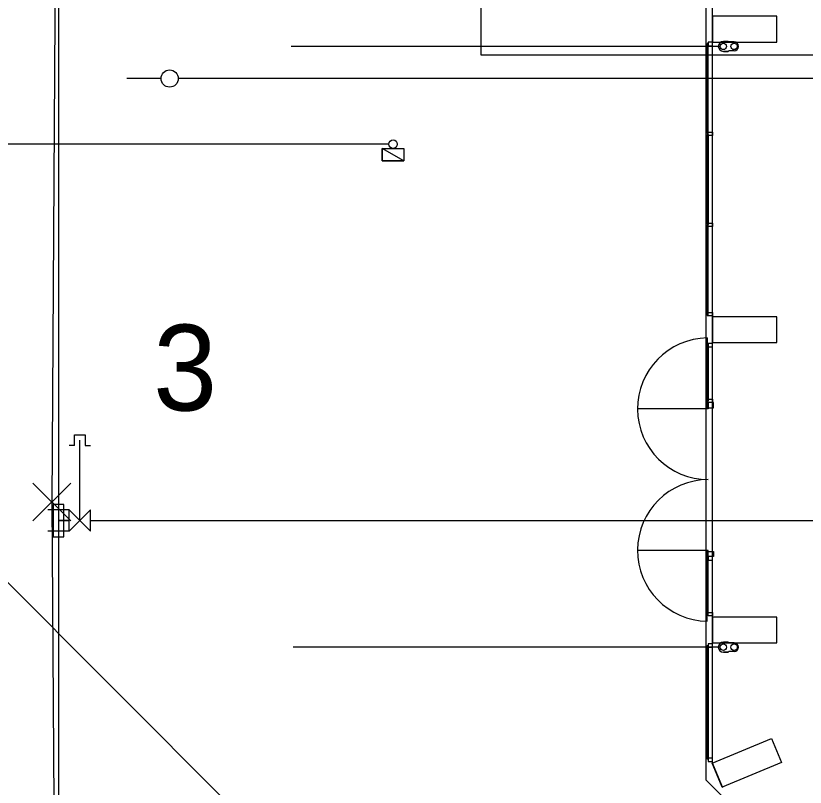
# Model space of a CAD drawing. Extents: x -263964 to -263544, y -1242317 to -1242020.
# Drawn here: x -263925.14 to -263906.73, y -1242227.54 to -1242209.57 of the extents above; entities that cross this region are included whole.
import ezdxf

# ---------------------------------------------------------------- set-up
doc = ezdxf.new("R2010")
doc.units = 0
for name, color, linetype in [('KFA_KOORDINACNA_SITUACIA_DSP_SEDA', 7, 'Continuous'), ('KFA_SO_50-2_POZIARNY_VODOVOD_BODY', 7, 'Continuous'), ('KFA_SO_50-2_POZIARNY_VODOVOD_TRASA', 7, 'Continuous')]:
    doc.layers.add(name, color=color, linetype=linetype)

msp = doc.modelspace()

# ---------------------------------------------------------------- linework, layer by layer
at = {"layer": 'KFA_KOORDINACNA_SITUACIA_DSP_SEDA'}
for p, q in [((-263924.143, -1242185.14), (-263924.143, -1242250.14)), ((-263908.893, -1242226.995), (-263908.893, -1242203.332)), ((-263907.398, -1242209.582), (-263908.898, -1242209.582)), ((-263908.898, -1242209.582), (-263908.898, -1242210.182)), ((-263907.398, -1242210.182), (-263907.398, -1242209.582)), ((-263908.718, -1242210.282), (-263918.714, -1242210.282)), ((-263909.018, -1242210.212), (-263909.018, -1242212.312)), ((-263908.993, -1242210.212), (-263909.018, -1242210.212)), ((-263908.893, -1242210.187), (-263908.993, -1242210.187)), ((-263908.993, -1242210.187), (-263908.993, -1242210.227)), ((-263908.993, -1242212.312), (-263908.993, -1242210.212)), ((-263908.993, -1242210.227), (-263908.993, -1242210.267)), ((-263908.993, -1242210.267), (-263908.893, -1242210.267)), ((-263908.898, -1242210.182), (-263907.398, -1242210.182)), ((-263908.893, -1242210.267), (-263908.893, -1242210.187)), ((-263908.532, -1242210.165), (-263908.643, -1242210.165)), ((-263908.518, -1242210.179), (-263908.532, -1242210.165)), ((-263908.393, -1242210.179), (-263908.518, -1242210.179)), ((-263908.643, -1242210.399), (-263908.532, -1242210.399)), ((-263908.532, -1242210.399), (-263908.643, -1242210.399)), ((-263908.518, -1242210.385), (-263908.532, -1242210.399)), ((-263908.393, -1242210.385), (-263908.518, -1242210.385)), ((-263921.751, -1242211.032), (-263922.551, -1242211.032)), ((-263903.343, -1242211.032), (-263921.351, -1242211.032)), ((-263909.018, -1242212.312), (-263908.993, -1242212.312)), ((-263909.018, -1242214.432), (-263909.018, -1242212.332)), ((-263909.018, -1242212.332), (-263908.993, -1242212.332)), ((-263908.993, -1242212.272), (-263908.993, -1242212.282)), ((-263908.993, -1242212.362), (-263908.993, -1242212.272)), ((-263908.993, -1242212.282), (-263908.893, -1242212.282)), ((-263908.993, -1242212.332), (-263908.993, -1242214.432)), ((-263908.893, -1242212.282), (-263908.893, -1242212.362)), ((-263908.893, -1242212.362), (-263908.993, -1242212.362)), ((-263916.443, -1242212.562), (-263925.798, -1242212.562)), ((-263916.593, -1242212.952), (-263916.593, -1242212.662)), ((-263916.593, -1242212.662), (-263916.093, -1242212.662)), ((-263916.093, -1242212.952), (-263916.593, -1242212.662)), ((-263916.093, -1242212.952), (-263916.593, -1242212.662)), ((-263916.593, -1242212.662), (-263916.593, -1242212.952)), ((-263916.093, -1242212.662), (-263916.093, -1242212.952)), ((-263916.093, -1242212.952), (-263916.593, -1242212.952)), ((-263916.593, -1242212.952), (-263916.093, -1242212.952)), ((-263908.993, -1242214.432), (-263909.018, -1242214.432)), ((-263909.018, -1242214.452), (-263909.018, -1242216.552)), ((-263908.993, -1242214.452), (-263909.018, -1242214.452)), ((-263908.993, -1242214.442), (-263908.993, -1242214.402)), ((-263908.993, -1242214.402), (-263908.893, -1242214.402)), ((-263908.993, -1242214.482), (-263908.993, -1242214.442)), ((-263908.993, -1242216.552), (-263908.993, -1242214.452)), ((-263908.893, -1242214.482), (-263908.993, -1242214.482)), ((-263908.893, -1242214.402), (-263908.893, -1242214.482)), ((-263909.018, -1242216.552), (-263908.993, -1242216.552)), ((-263908.993, -1242216.522), (-263908.993, -1242216.482)), ((-263908.993, -1242216.482), (-263908.893, -1242216.482)), ((-263908.993, -1242216.562), (-263908.993, -1242216.522)), ((-263908.893, -1242216.562), (-263908.993, -1242216.562)), ((-263907.398, -1242216.582), (-263908.898, -1242216.582)), ((-263908.898, -1242216.582), (-263908.898, -1242217.182)), ((-263908.893, -1242216.482), (-263908.893, -1242216.562)), ((-263907.398, -1242217.182), (-263907.398, -1242216.582)), ((-263909.018, -1242217.077), (-263909.018, -1242218.727)), ((-263909.018, -1242218.542), (-263909.018, -1242217.242)), ((-263909.018, -1242217.242), (-263908.993, -1242217.242)), ((-263908.893, -1242217.202), (-263908.993, -1242217.202)), ((-263908.993, -1242217.202), (-263908.993, -1242217.242)), ((-263908.993, -1242217.242), (-263908.993, -1242218.542)), ((-263908.993, -1242217.242), (-263908.993, -1242217.282)), ((-263908.993, -1242217.282), (-263908.893, -1242217.282)), ((-263908.898, -1242217.182), (-263907.398, -1242217.182)), ((-263908.893, -1242217.282), (-263908.893, -1242217.202)), ((-263908.993, -1242218.542), (-263909.018, -1242218.542)), ((-263908.993, -1242218.542), (-263908.993, -1242218.502)), ((-263908.993, -1242218.502), (-263908.893, -1242218.502)), ((-263908.993, -1242218.582), (-263908.993, -1242218.542)), ((-263908.893, -1242218.582), (-263908.993, -1242218.582)), ((-263908.873, -1242218.582), (-263908.993, -1242218.582)), ((-263908.993, -1242218.582), (-263908.993, -1242218.702)), ((-263908.893, -1242218.502), (-263908.893, -1242218.582)), ((-263908.873, -1242218.702), (-263908.873, -1242218.582)), ((-263908.993, -1242218.727), (-263910.643, -1242218.727)), ((-263908.993, -1242218.702), (-263908.993, -1242218.727)), ((-263908.993, -1242218.702), (-263908.873, -1242218.702)), ((-263923.768, -1242219.582), (-263923.768, -1242219.332)), ((-263923.768, -1242219.332), (-263923.518, -1242219.332)), ((-263923.518, -1242219.332), (-263923.518, -1242219.582)), ((-263923.643, -1242221.332), (-263923.643, -1242219.457)), ((-263923.768, -1242219.582), (-263923.893, -1242219.582)), ((-263923.518, -1242219.582), (-263923.393, -1242219.582)), ((-263924.018, -1242220.957), (-263924.268, -1242220.957)), ((-263924.268, -1242220.957), (-263924.268, -1242221.707)), ((-263924.018, -1242221.707), (-263924.018, -1242220.957)), ((-263923.893, -1242221.082), (-263924.393, -1242221.082)), ((-263923.893, -1242221.582), (-263923.893, -1242221.082)), ((-263923.893, -1242221.082), (-263923.393, -1242221.582)), ((-263923.393, -1242221.082), (-263923.893, -1242221.582)), ((-263923.393, -1242221.582), (-263923.393, -1242221.082)), ((-263924.143, -1242221.332), (-263923.893, -1242221.332)), ((-263923.893, -1242221.332), (-263924.143, -1242221.332)), ((-263923.393, -1242221.332), (-263903.343, -1242221.332)), ((-263923.893, -1242221.582), (-263924.393, -1242221.582)), ((-263924.268, -1242221.707), (-263924.018, -1242221.707)), ((-263916.414, -1242231.691), (-263926.24, -1242221.865)), ((-263908.993, -1242222.027), (-263910.643, -1242222.027)), ((-263909.018, -1242223.677), (-263909.018, -1242222.027)), ((-263908.993, -1242222.052), (-263908.993, -1242222.027)), ((-263908.993, -1242222.052), (-263908.873, -1242222.052)), ((-263908.993, -1242222.172), (-263908.993, -1242222.052)), ((-263908.873, -1242222.052), (-263908.873, -1242222.172)), ((-263909.018, -1242222.212), (-263909.018, -1242223.512)), ((-263908.993, -1242222.212), (-263909.018, -1242222.212)), ((-263908.893, -1242222.172), (-263908.993, -1242222.172)), ((-263908.993, -1242222.172), (-263908.993, -1242222.212)), ((-263908.873, -1242222.172), (-263908.993, -1242222.172)), ((-263908.993, -1242223.512), (-263908.993, -1242222.212)), ((-263908.993, -1242222.212), (-263908.993, -1242222.252)), ((-263908.993, -1242222.252), (-263908.893, -1242222.252)), ((-263908.893, -1242222.252), (-263908.893, -1242222.172)), ((-263909.018, -1242223.512), (-263908.993, -1242223.512)), ((-263908.993, -1242223.512), (-263908.993, -1242223.472)), ((-263908.993, -1242223.472), (-263908.893, -1242223.472)), ((-263908.993, -1242223.552), (-263908.993, -1242223.512)), ((-263908.893, -1242223.552), (-263908.993, -1242223.552)), ((-263907.398, -1242223.582), (-263908.898, -1242223.582)), ((-263908.898, -1242223.582), (-263908.898, -1242224.182)), ((-263908.893, -1242223.472), (-263908.893, -1242223.552)), ((-263907.398, -1242224.182), (-263907.398, -1242223.582)), ((-263908.718, -1242224.282), (-263918.67, -1242224.282)), ((-263909.018, -1242226.892), (-263909.018, -1242224.242)), ((-263909.018, -1242224.242), (-263908.993, -1242224.242)), ((-263908.893, -1242224.202), (-263908.993, -1242224.202)), ((-263908.993, -1242224.202), (-263908.993, -1242224.242)), ((-263908.993, -1242224.242), (-263908.993, -1242226.892)), ((-263908.993, -1242224.242), (-263908.993, -1242224.282)), ((-263908.993, -1242224.282), (-263908.893, -1242224.282)), ((-263908.898, -1242224.182), (-263907.398, -1242224.182)), ((-263908.893, -1242224.282), (-263908.893, -1242224.202)), ((-263908.532, -1242224.165), (-263908.643, -1242224.165)), ((-263908.518, -1242224.179), (-263908.532, -1242224.165)), ((-263908.393, -1242224.179), (-263908.518, -1242224.179)), ((-263908.643, -1242224.399), (-263908.532, -1242224.399)), ((-263908.532, -1242224.399), (-263908.643, -1242224.399)), ((-263908.518, -1242224.385), (-263908.532, -1242224.399)), ((-263908.393, -1242224.385), (-263908.518, -1242224.385)), ((-263908.903, -1242226.985), (-263907.518, -1242226.411)), ((-263907.518, -1242226.411), (-263907.288, -1242226.966)), ((-263908.993, -1242226.892), (-263909.018, -1242226.892)), ((-263908.893, -1242226.865), (-263908.993, -1242226.865)), ((-263908.993, -1242226.865), (-263908.993, -1242226.905)), ((-263908.893, -1242226.945), (-263908.893, -1242226.865)), ((-263908.993, -1242226.905), (-263908.993, -1242226.945)), ((-263908.993, -1242226.945), (-263908.893, -1242226.945)), ((-263908.674, -1242227.54), (-263908.903, -1242226.985)), ((-263908.893, -1242226.995), (-263908.663, -1242227.55)), ((-263907.288, -1242226.966), (-263908.674, -1242227.54))]:
    msp.add_line(p, q, dxfattribs=at)
msp.add_lwpolyline([(-263794.893, -1242227.382), (-263808.968, -1242241.457), (-263894.968, -1242241.457), (-263909.043, -1242227.382), (-263909.043, -1242196.333), (-263914.143, -1242196.333), (-263914.143, -1242132.433), (-263909.043, -1242132.433), (-263909.043, -1242101.382), (-263894.968, -1242087.307), (-263808.968, -1242087.307), (-263794.893, -1242101.382), (-263794.893, -1242227.382)], dxfattribs=at)
msp.add_lwpolyline([(-263893.618, -1242118.282), (-263916.093, -1242118.282), (-263916.093, -1242175.482), (-263914.293, -1242175.482), (-263914.293, -1242210.482), (-263893.618, -1242210.482), (-263893.618, -1242166.382), (-263900.043, -1242166.382), (-263900.043, -1242162.382), (-263893.618, -1242162.382)], close=True, dxfattribs=at)
for centre, radius in [((-263908.643, -1242210.282), 0.075), ((-263908.393, -1242210.282), 0.075), ((-263921.551, -1242211.032), 0.2), ((-263916.343, -1242212.562), 0.1), ((-263908.643, -1242224.282), 0.075), ((-263908.393, -1242224.282), 0.075)]:
    msp.add_circle(centre, radius, dxfattribs=at)
for centre, radius, start, end in [((-263908.643, -1242210.282), 0.117, 90, 270), ((-263908.393, -1242210.282), 0.103, 270, 90), ((-263908.993, -1242218.727), 1.65, 90.8682, 270), ((-263908.993, -1242222.027), 1.65, 90, 269.1318), ((-263908.643, -1242224.282), 0.117, 90, 270), ((-263908.393, -1242224.282), 0.103, 270, 90)]:
    msp.add_arc(centre, radius, start, end, dxfattribs=at)
at = {"layer": 'KFA_SO_50-2_POZIARNY_VODOVOD_BODY'}
for p, q in [((-263924.738, -1242221.341), (-263923.854, -1242220.457)), ((-263923.854, -1242221.341), (-263924.738, -1242220.457)), ((-263924.296, -1242220.899), (-263924.296, -1242220.899))]:
    msp.add_line(p, q, dxfattribs=at)
at = {"layer": 'KFA_SO_50-2_POZIARNY_VODOVOD_TRASA'}
msp.add_lwpolyline([(-263924.931, -1242185.127), (-263924.146, -1242197.091), (-263924.296, -1242220.899), (-263924.1, -1242250.121), (-263913.986, -1242249.798), (-263886.91, -1242249.876), (-263867.714, -1242249.83), (-263837.257, -1242249.836), (-263828.162, -1242249.901), (-263787.99, -1242250.032), (-263788.202, -1242220.837), (-263788.195, -1242200.509), (-263788.092, -1242179.915), (-263788.062, -1242148.958), (-263787.919, -1242127.952), (-263787.952, -1242110.966), (-263788.129, -1242082.536), (-263828.429, -1242082.723), (-263836.783, -1242082.559), (-263867.306, -1242082.615), (-263886.71, -1242082.472), (-263924.08, -1242082.613), (-263924.644, -1242106.322), (-263924.479, -1242117.427)], close=True, dxfattribs=at)

# ---------------------------------------------------------------- texts
at = {"layer": 'KFA_SO_50-2_POZIARNY_VODOVOD_BODY'}
msp.add_text('3', height=2, dxfattribs=at).set_placement((-263921.933, -1242218.768))

doc.saveas('drawing.dxf')
